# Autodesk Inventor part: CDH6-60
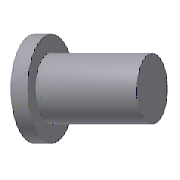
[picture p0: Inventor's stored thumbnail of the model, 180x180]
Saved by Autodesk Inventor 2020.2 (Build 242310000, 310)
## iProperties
Manager: www.cadconsulting.pl
Company: Fabian Stasiak CAD Consulting
IsCustomPart: 1
Created: 2014-02
Part Number: CDH6-60
Material: SKD61
Description: Straight Core Pin
Document SubType Name: Modeling
Designer: F.Stasiak
Standard Revision: 1
Manufacturer: PUNCH
Language: pl-PL
Size Designation: 6-60
Categories: <MemberInstance><Categories><Category DisplayName="Forma wtryskowa" InternalName="349578f2-f4d4-4954-8c09-8e99297a61c0" Mnemonic="MOLD"><Category DisplayName="W
Mass: 1.61494 g
Surface Area: 11.4822 cm^2
Volume: 1.61494 cm^3
Density: 7.8 g/cm^3
Appearance: Aluminium - ciemne
Catalog Web Link: www.expertbooks.pl
Author: F.Stasiak
Subject: Zbiór ćwiczeń. Autodesk Inventor 2020. Kurs Professional
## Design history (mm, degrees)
sketch "Sketch1"
  geometry: L1 (4.5, 0)-(4.5, 4); L2 (4.5, 4)-(3, 4); L3 (3, 4)-(3, 60); L4 (3, 60)-(0, 60); L5 (4.5, 0)-(0, 0); L6 (0, 0)-(0, 60); L7 (0, 60)-(0, -10) reference; 1 further point
  constraints: 14 end point, 2 horizontal, 1 coincident, 1 collinear, 1 parallel
  dimensions: "d2" = 4 distance of L1.start L1.end (= T_); "d19" = 60 distance between parallel lines of L4 L5 (= L); "d38" = 6 diameter of L3 L7 (= P); "d39" = 9 diameter of L1 L7 (= H_)
revolve "Revolution1" sketch "Sketch1" stored, may be unused: angle "d4" = 90 deg
fillet "Fillet1" dims "d36" = 0.3
workplane "Work Plane1"
sketch "Sketch2"
  geometry: 2 further points
  constraints: 1 vertical alignment
  dimensions: "d21" = 2 distance of point (0, -2) point (0, 0) (= 0.5 x T_)
hole "Anti_Rotary Hole" sketch "Sketch2" at (0, 0) diameter "d22" = 0.8 (= Anti_Rotary_D); stored, may be unused: countersink angle "d26" = 90 deg, drill point angle "d28" = 118 deg; dims "d23" = 6, "d24" = 4, "d25" = 2, "d27" = 1.2 (= 1.5 x Anti_Rotary_D)
sketch "Sketch3"
  geometry: L1 (-3.3, 3.059)-(-3.3, -3.059); A1 r 4.5 centre (0, 0) between (-3.3, 3.059) and (-3.3, -3.059) reference; 1 further point
  constraints: 2 end point, 2 point on circle, 1 vertical
  dimensions: "d29" = 3.3 distance from line of point (0, 0) L1 (= Anti_Rotary_P)
extrude "Anti_Rotary Plane" cut sketch "Sketch3" extent not by distance; stored distance "d30" = 10; taper "d31" = 0 deg
body "Solid1"
other parameters: "H_" = 9 [user parameter; used in 1 equation term], "L" = 60 [user parameter; used in 1 equation term], "P" = 6 [user parameter; used in 1 equation term], "d7" = 0, "d8" = 0, "T_" = 4 [user parameter; used in 2 equation terms], "Anti_Rotary_P" = 3.3 [user parameter; used in 1 equation term], "Anti_Rotary_D" = 0.8 [user parameter; used in 2 equation terms], "d32" = 0, "d33" = 0, "d34" = 0, "d35" = 0, "IsARPlane" = 0 [user parameter], "IsARHole" = 0 [user parameter]
